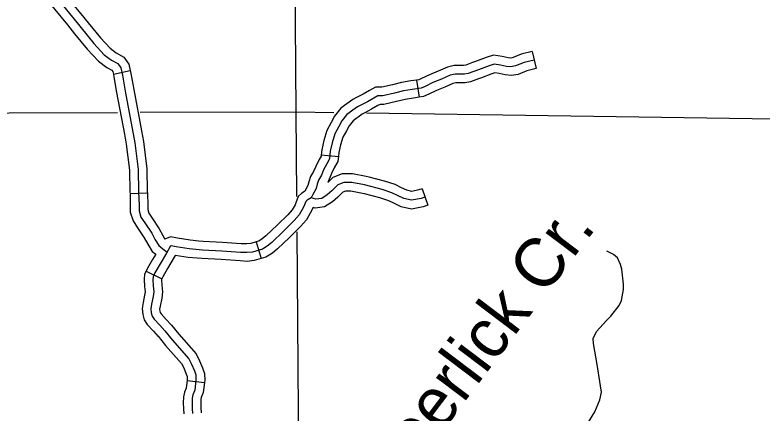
# Model space of a CAD drawing. Extents: x -19 to 366, y -4 to 359.
# Drawn here: x 130.017 to 131.239, y 200.589 to 201.24 of the extents above; entities that cross this region are included whole.
import ezdxf

# ---------------------------------------------------------------- set-up
doc = ezdxf.new("R2010")
doc.units = 0
for name, color, linetype in [('Level 35', 7, 'Continuous'), ('Level 45', 7, 'Continuous'), ('Level 5', 7, 'Continuous'), ('Level 60', 7, 'Continuous')]:
    doc.layers.add(name, color=color, linetype=linetype)

msp = doc.modelspace()

# ---------------------------------------------------------------- linework, layer by layer
at = {"layer": 'Level 35'}
for points in [[(130.9844, 200.7404), (130.9916, 200.7476), (131.0048, 200.7647), (131.0086, 200.773), (131.012, 200.7909), (131.012, 200.7996), (131.0093, 200.8243), (131.0074, 200.8322), (131.0021, 200.8429), (130.996, 200.8482), (130.985, 200.8539)], [(130.9548, 200.5738), (130.965, 200.5909), (130.9733, 200.6106), (130.9759, 200.6232), (130.969, 200.6683), (130.9629, 200.7028), (130.9625, 200.7108), (130.9678, 200.7222), (130.9844, 200.7404)]]:
    msp.add_lwpolyline(points, dxfattribs=at)
at = {"layer": 'Level 45'}
for p, q in [((130.8627, 201.1804), (130.8691, 201.1528)), ((130.1776, 201.1434), (130.2054, 201.1493)), ((130.6736, 201.1337), (130.6778, 201.1056)), ((130.5176, 201.0114), (130.5459, 201.0087)), ((130.2049, 200.9482), (130.2333, 200.9491)), ((130.6829, 200.9557), (130.6919, 200.9288)), ((130.4114, 200.8691), (130.4194, 200.8418)), ((130.2312, 200.8209), (130.2568, 200.8087)), ((130.2984, 200.6421), (130.3266, 200.6389))]:
    msp.add_line(p, q, dxfattribs=at)
for points in [[(130.0878, 201.3029), (130.0889, 201.2916), (130.0925, 201.2822), (130.1043, 201.2669), (130.1245, 201.2424), (130.1364, 201.2276)], [(130.0595, 201.3004), (130.0609, 201.2852), (130.0674, 201.2681), (130.0821, 201.2492), (130.1024, 201.2244), (130.1143, 201.2097)], [(130.0932, 201.2581), (130.1134, 201.2334), (130.1457, 201.1935), (130.1628, 201.1752), (130.1748, 201.1663), (130.1849, 201.1607), (130.1899, 201.1537), (130.1925, 201.1417), (130.1969, 201.1157), (130.2127, 201.031), (130.2184, 200.9874), (130.219, 200.9507), (130.2196, 200.9285), (130.2196, 200.9197), (130.2228, 200.9096), (130.2291, 200.9001), (130.2405, 200.883), (130.2462, 200.8722), (130.2519, 200.8628)], [(130.1364, 201.2276), (130.1564, 201.2029), (130.1722, 201.1858), (130.1825, 201.1783), (130.1945, 201.1715), (130.2032, 201.1596), (130.2054, 201.1493)], [(130.1143, 201.2097), (130.135, 201.1842), (130.1533, 201.1646), (130.167, 201.1544), (130.1752, 201.1498), (130.1767, 201.1478), (130.1776, 201.1434)], [(130.8627, 201.1804), (130.8449, 201.1763), (130.8314, 201.1705), (130.8276, 201.1698), (130.8232, 201.1703), (130.8136, 201.1723), (130.7997, 201.1745), (130.7876, 201.1708), (130.7698, 201.164), (130.765, 201.1623)], [(130.8659, 201.1666), (130.8494, 201.1628), (130.8355, 201.1569), (130.8281, 201.1555), (130.821, 201.1562), (130.811, 201.1583), (130.8007, 201.1599), (130.7922, 201.1573), (130.7748, 201.1507), (130.758, 201.1445), (130.7518, 201.1434), (130.7428, 201.1433), (130.7367, 201.1435), (130.7287, 201.1417), (130.7142, 201.1352), (130.7005, 201.1297), (130.6879, 201.1234), (130.6812, 201.1205), (130.6664, 201.1182), (130.652, 201.1161), (130.6374, 201.1123), (130.6183, 201.1082), (130.6103, 201.1081), (130.6036, 201.1044), (130.5931, 201.0984), (130.5771, 201.0899), (130.5598, 201.0774), (130.5515, 201.067), (130.5465, 201.0576), (130.54, 201.0458), (130.5355, 201.0312), (130.5324, 201.0172), (130.5312, 201.0048), (130.5266, 200.9968), (130.5215, 200.9867), (130.5179, 200.9779), (130.5133, 200.97), (130.5109, 200.9632), (130.5092, 200.9561), (130.5033, 200.9452), (130.5011, 200.9412)], [(130.765, 201.1623), (130.7542, 201.1583), (130.7504, 201.1576), (130.743, 201.1575), (130.7354, 201.1578), (130.7242, 201.1552), (130.7087, 201.1482), (130.6947, 201.1426), (130.6819, 201.1363), (130.6772, 201.1342), (130.6736, 201.1337)], [(130.1776, 201.1434), (130.1785, 201.139), (130.1829, 201.1132), (130.1956, 201.0454)], [(130.2054, 201.1493), (130.2064, 201.1443), (130.2109, 201.1182), (130.2235, 201.0506)], [(130.8691, 201.1528), (130.8538, 201.1492), (130.8397, 201.1432), (130.8287, 201.1411), (130.8188, 201.1422), (130.8085, 201.1443), (130.8017, 201.1454), (130.7968, 201.1439), (130.7798, 201.1374), (130.7749, 201.1356)], [(130.6736, 201.1337), (130.6643, 201.1323), (130.6491, 201.13), (130.6342, 201.1261), (130.6168, 201.1224), (130.6066, 201.1223), (130.5966, 201.1168), (130.5862, 201.1108), (130.5744, 201.1045)], [(130.7749, 201.1356), (130.7618, 201.1308), (130.7532, 201.1292), (130.7426, 201.1291), (130.738, 201.1292), (130.7332, 201.1281), (130.7198, 201.1221), (130.7063, 201.1167), (130.6939, 201.1105), (130.6851, 201.1067), (130.6778, 201.1056)], [(130.6778, 201.1056), (130.6686, 201.1042), (130.6549, 201.1021), (130.6407, 201.0985), (130.6199, 201.094), (130.614, 201.0939), (130.6105, 201.092), (130.6, 201.086), (130.5877, 201.0794)], [(130.5744, 201.1045), (130.5695, 201.102), (130.5499, 201.0878), (130.5396, 201.0748), (130.534, 201.0644), (130.5268, 201.0514), (130.5218, 201.0348), (130.5184, 201.0194), (130.5176, 201.0114)], [(130.5877, 201.0794), (130.5846, 201.0778), (130.5697, 201.067), (130.5634, 201.0591), (130.559, 201.0508), (130.5532, 201.0403), (130.5493, 201.0276), (130.5465, 201.015), (130.5459, 201.0087)], [(130.1956, 201.0454), (130.1987, 201.0288), (130.2042, 200.9863), (130.2048, 200.9503), (130.2049, 200.9482)], [(130.2235, 201.0506), (130.2267, 201.0332), (130.2326, 200.9884), (130.2332, 200.951), (130.2333, 200.9491)], [(130.5176, 201.0114), (130.5174, 201.0093), (130.5141, 201.0036), (130.5086, 200.9925), (130.5052, 200.9842), (130.5003, 200.9759), (130.4973, 200.9673), (130.4958, 200.9613), (130.4908, 200.9519), (130.4905, 200.9513), (130.4861, 200.9487), (130.4801, 200.9434), (130.4764, 200.9327), (130.4748, 200.9298)], [(130.5459, 201.0087), (130.5451, 201.0003), (130.5391, 200.9901), (130.5345, 200.9808), (130.5284, 200.966)], [(130.5959, 200.9749), (130.5914, 200.9761), (130.569, 200.9803), (130.5517, 200.9805), (130.5367, 200.9743), (130.5284, 200.966)], [(130.6829, 200.9557), (130.6773, 200.9539), (130.6657, 200.9516), (130.6576, 200.9534), (130.6488, 200.9576), (130.6388, 200.9627), (130.6214, 200.9681), (130.5959, 200.9749)], [(130.6874, 200.9423), (130.6809, 200.9401), (130.6655, 200.9371), (130.6529, 200.9399), (130.6426, 200.9448), (130.6334, 200.9495), (130.6175, 200.9545), (130.5883, 200.9622), (130.5676, 200.9661), (130.5544, 200.9663), (130.5448, 200.9623), (130.5351, 200.9526), (130.5276, 200.9457), (130.5184, 200.9401), (130.5088, 200.9389), (130.5011, 200.9412)], [(130.2049, 200.9482), (130.2054, 200.9283), (130.2054, 200.9175), (130.2099, 200.9034), (130.2173, 200.8922), (130.2283, 200.8757), (130.2338, 200.8653), (130.2412, 200.853), (130.247, 200.8488)], [(130.2333, 200.9491), (130.2338, 200.9287), (130.2338, 200.9218), (130.2358, 200.9157), (130.2409, 200.9079), (130.2527, 200.8903), (130.2586, 200.8792), (130.262, 200.8736)], [(130.5886, 200.9474), (130.5851, 200.9483), (130.5661, 200.9519), (130.5572, 200.952), (130.5528, 200.9502), (130.5449, 200.9423), (130.5362, 200.9343), (130.5232, 200.9264), (130.5077, 200.9244), (130.5047, 200.9252)], [(130.6919, 200.9288), (130.6845, 200.9263), (130.6653, 200.9226), (130.6482, 200.9263), (130.6363, 200.9321), (130.628, 200.9363), (130.6135, 200.9408), (130.5886, 200.9474)], [(130.5011, 200.9412), (130.4946, 200.9372), (130.4923, 200.9352), (130.4894, 200.9269), (130.4818, 200.9131), (130.4734, 200.9037), (130.4558, 200.8865), (130.4366, 200.8681), (130.4295, 200.8622), (130.4214, 200.8572), (130.4051, 200.8524), (130.3962, 200.8514), (130.3857, 200.8518), (130.355, 200.854), (130.3234, 200.8556), (130.3018, 200.8575), (130.2802, 200.8608), (130.2724, 200.8623), (130.2703, 200.8615), (130.2645, 200.8507), (130.2541, 200.8328), (130.2457, 200.8184), (130.2426, 200.8119), (130.2421, 200.807), (130.2427, 200.7969), (130.2437, 200.787), (130.2429, 200.7793), (130.2403, 200.7668), (130.2389, 200.7594), (130.2397, 200.7528), (130.2413, 200.7474), (130.2444, 200.7427), (130.2536, 200.7324), (130.2616, 200.7236), (130.2739, 200.7088), (130.3011, 200.6778), (130.3057, 200.6686), (130.3103, 200.6577), (130.3125, 200.6512), (130.3127, 200.6426), (130.3116, 200.6323), (130.3109, 200.626), (130.3078, 200.6188), (130.3065, 200.6133), (130.3063, 200.6059), (130.3068, 200.5964), (130.3072, 200.5882)], [(130.4748, 200.9298), (130.4701, 200.9214), (130.4631, 200.9135), (130.446, 200.8967), (130.4271, 200.8787), (130.4212, 200.8737), (130.4156, 200.8703), (130.4114, 200.8691)], [(130.5047, 200.9252), (130.4996, 200.916)], [(130.4996, 200.916), (130.4934, 200.9049), (130.4837, 200.8939), (130.4657, 200.8763), (130.4461, 200.8575), (130.4378, 200.8506), (130.4273, 200.8441), (130.4194, 200.8418)], [(130.3173, 200.8704), (130.3035, 200.8717), (130.2826, 200.8748), (130.2712, 200.877), (130.262, 200.8736)], [(130.2519, 200.8628), (130.2588, 200.8577), (130.2654, 200.8522)], [(130.4114, 200.8691), (130.4023, 200.8664), (130.3956, 200.8656), (130.3865, 200.866), (130.3559, 200.8682), (130.3244, 200.8698), (130.3173, 200.8704)], [(130.247, 200.8488), (130.2418, 200.8399), (130.2332, 200.8251), (130.2312, 200.8209)], [(130.3148, 200.8421), (130.3001, 200.8434), (130.2785, 200.8467), (130.277, 200.8438), (130.2664, 200.8256), (130.2583, 200.8118), (130.2568, 200.8087)], [(130.4194, 200.8418), (130.408, 200.8385), (130.3967, 200.8371), (130.3848, 200.8377), (130.3542, 200.8399), (130.3225, 200.8415), (130.3148, 200.8421)], [(130.2312, 200.8209), (130.2288, 200.8159), (130.2278, 200.8073), (130.2286, 200.7957), (130.2295, 200.7871), (130.2288, 200.7815), (130.2264, 200.7695), (130.2246, 200.76), (130.2257, 200.75), (130.2283, 200.7413), (130.2331, 200.734), (130.2431, 200.7229), (130.2509, 200.7143), (130.2508, 200.7144)], [(130.2568, 200.8087), (130.2565, 200.8079), (130.2563, 200.8066), (130.2569, 200.7981), (130.258, 200.787), (130.2569, 200.7771), (130.2543, 200.764), (130.2533, 200.7589), (130.2536, 200.7557), (130.2543, 200.7535), (130.2557, 200.7514), (130.2642, 200.7419), (130.2723, 200.733), (130.2726, 200.7326)], [(130.2726, 200.7326), (130.2847, 200.718), (130.3129, 200.6858), (130.3186, 200.6745), (130.3236, 200.6627), (130.3266, 200.6537), (130.327, 200.642), (130.3266, 200.6389)], [(130.2508, 200.7144), (130.2631, 200.6996), (130.2892, 200.6697), (130.2928, 200.6626), (130.297, 200.6527), (130.2983, 200.6486), (130.2985, 200.6432), (130.2984, 200.6421)], [(130.2984, 200.6421), (130.2975, 200.6339), (130.297, 200.6297), (130.2942, 200.6232), (130.2923, 200.6151), (130.2921, 200.6057), (130.2926, 200.5957), (130.293, 200.5874)], [(130.3266, 200.6389), (130.3257, 200.6307), (130.3247, 200.6224), (130.3213, 200.6144), (130.3206, 200.6115), (130.3205, 200.6061), (130.321, 200.5971), (130.3214, 200.5889)]]:
    msp.add_lwpolyline(points, dxfattribs=at)
at = {"layer": 'Level 5'}
for points in [[(130.4768, 201.0812), (130.4733, 201.5229)], [(130.4768, 201.0812), (130.2216, 201.0805)], [(130.5381, 201.0803), (130.4768, 201.0812)], [(130.4778, 200.9431), (130.4768, 201.0812)], [(130.1846, 201.0804), (129.4755, 201.0782)], [(131.4827, 201.0664), (130.5919, 201.0795)], [(130.4827, 200.298), (130.4782, 200.8852)]]:
    msp.add_lwpolyline(points, dxfattribs=at)
at = {"layer": 'Level 60'}
for points in [[(132.1027, 1.3746), (131.9232, 9.99), (131.7429, 18.6056), (131.5621, 27.2214), (131.3806, 35.8373), (131.1985, 44.4533), (131.0158, 53.0695), (130.8324, 61.6859), (130.6485, 70.3024), (130.4639, 78.919), (130.2786, 87.5358), (130.0928, 96.1527), (129.9063, 104.7698), (129.7193, 113.387), (129.5316, 122.0044), (129.3433, 130.6219), (129.1543, 139.2396), (128.9648, 147.8575), (128.7746, 156.4754), (128.5838, 165.0936), (128.3925, 173.7119), (128.2005, 182.3303), (128.0078, 190.9489), (127.8146, 199.5676), (127.6208, 208.1865), (127.4264, 216.8056), (127.2313, 225.4247), (127.0357, 234.0441), (126.8394, 242.6636), (126.6425, 251.2833), (126.4451, 259.9031), (126.247, 268.523), (126.0483, 277.1431), (125.849, 285.7634), (125.6492, 294.3838), (125.4487, 303.0044), (125.2476, 311.6252), (125.0459, 320.2461), (124.8437, 328.8671), (124.6408, 337.4883), (124.4373, 346.1097)], [(0, 198.1326), (7.1014, 198.137), (14.2028, 198.1503), (21.3042, 198.1724), (28.4055, 198.2034), (35.5068, 198.2433), (42.6081, 198.292), (49.7092, 198.3496), (56.8103, 198.4161), (63.9113, 198.4913), (71.0123, 198.5755), (78.1131, 198.6685), (85.2137, 198.7704), (92.3143, 198.8811), (99.4147, 199.0007), (106.5149, 199.1291), (113.615, 199.2664), (120.7149, 199.4126), (127.8146, 199.5676), (134.9141, 199.7315), (142.0135, 199.9042), (149.1125, 200.0858), (156.2114, 200.2762), (163.31, 200.4755), (170.4084, 200.6837), (177.5065, 200.9007), (184.6043, 201.1265), (191.7018, 201.3612), (198.799, 201.6048), (205.896, 201.8572), (212.9926, 202.1185), (220.0888, 202.3886), (227.1848, 202.6676), (234.2803, 202.9554), (241.3755, 203.2521), (248.4704, 203.5576), (255.5648, 203.872), (262.6589, 204.1952), (269.7525, 204.5273), (276.8457, 204.8682), (283.9385, 205.218), (291.0309, 205.5766), (298.1228, 205.9441), (305.2142, 206.3204), (312.3051, 206.7056), (319.3956, 207.0996), (326.4856, 207.5024), (333.5751, 207.9141), (340.664, 208.3347)]]:
    msp.add_spline(points, degree=3, dxfattribs=at)

# ---------------------------------------------------------------- texts
at = {"layer": 'Level 35'}
msp.add_text('Deerlick Cr.', height=0.08, rotation=52.8884, dxfattribs=at).set_placement((130.6316, 200.4471))

doc.saveas('drawing.dxf')
